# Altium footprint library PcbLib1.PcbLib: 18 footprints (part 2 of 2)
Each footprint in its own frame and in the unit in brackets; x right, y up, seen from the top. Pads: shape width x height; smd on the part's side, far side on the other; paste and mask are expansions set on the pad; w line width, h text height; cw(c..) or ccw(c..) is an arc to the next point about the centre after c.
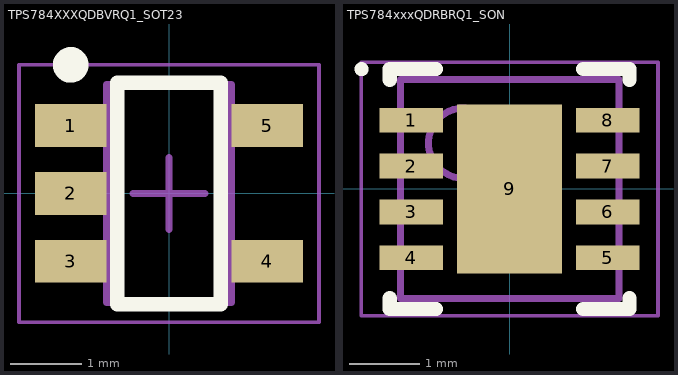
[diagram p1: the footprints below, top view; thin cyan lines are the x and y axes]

## TPS784XXXQDBVRQ1_SOT23 [mm] "SOT23, 5-Leads, Body 2,90x2,80mm, Pitch 0,95mm, IPC Medium Density"
height 1.45
pads (5):
  rect 1x0.6 smd: 1(-1.375,0.95) 2(-1.375,0) 3(-1.375,-0.95) 4(1.375,-0.95) 5(1.375,0.95)
Top Overlay:
  circle w0.25: c-1.375,1.8 r0.125
  lines w0.2: -0.725,-1.55 0.725,-1.55 0.725,1.55 -0.725,1.55 -0.725,-1.55
Top Courtyard:
  lines w0.05: -2.1,-1.8 -2.1,1.8 2.1,1.8 2.1,-1.8 -2.1,-1.8
  lines w0.1: -0.5,0 0.5,0 ; 0,-0.5 0,0.5
Mechanical 13:
  lines w0.1: -0.875,-1.525 -0.875,1.525 0.875,1.525 0.875,-1.525 -0.875,-1.525
3D body: height 1.45, standoff 0.05, extent -0.875,-1.525 0.875,1.525

## TPS784xxxQDRBRQ1_SON [mm] "SON127P600-8N"
height 1
pads (9):
  rect 0.9x0.35 smd: 1(-1.395,0.975) 2(-1.395,0.325) 3(-1.395,-0.325) 4(-1.395,-0.975) 5(1.395,-0.975) 6(1.395,-0.325) 7(1.395,0.325) 8(1.395,0.975)
  rect 1.49x2.4 smd: 9(0,0)
Top Overlay:
  circle w0.1: c-2.1,1.7 r0.05
  lines w0.2: -1.7,-1.55 -1.7,-1.7 -1.045,-1.7 ; -1.7,1.55 -1.7,1.7 -1.045,1.7 ; 1.045,-1.7 1.7,-1.7 1.7,-1.55 ; 1.045,1.7 1.7,1.7 1.7,1.55
Top Courtyard:
  lines w0.05: -2.105,-1.8 -2.105,1.8 2.105,1.8 2.105,-1.8 -2.105,-1.8
  lines w0.1: -0.5,0 0.5,0 ; 0,-0.5 0,0.5
Mechanical 13:
  circle w0.1: c-0.65,0.65 r0.5
  lines w0.1: -1.55,-1.55 -1.55,1.55 1.55,1.55 1.55,-1.55 -1.55,-1.55
3D body: height 1, standoff 0, extent -1.55,-1.55 1.55,1.55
